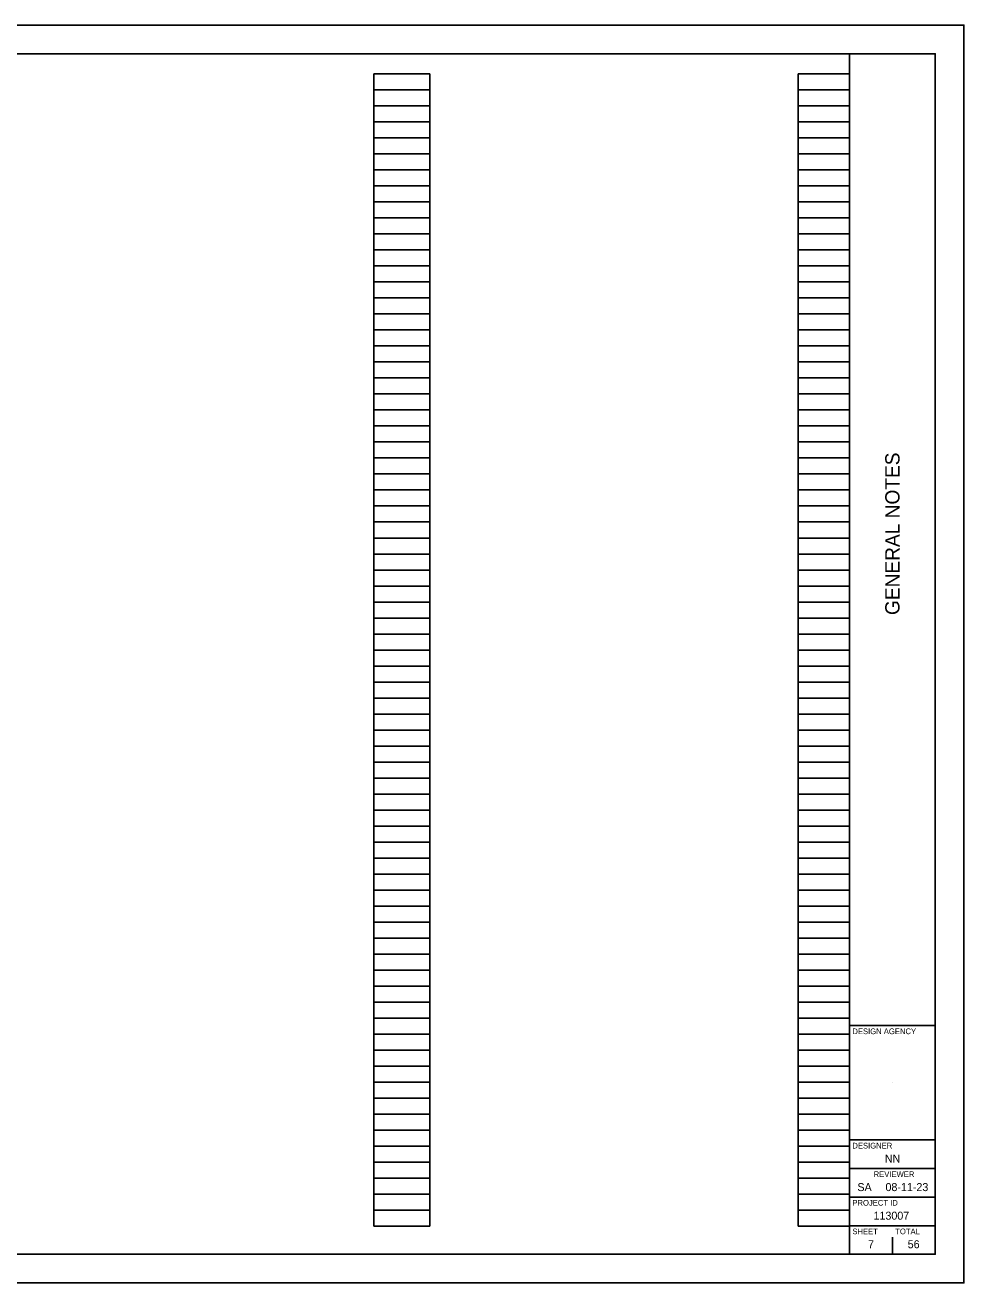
# Model space of a CAD drawing. Extents: x 0 to 34, y -7.4 to 22.
# Drawn here: x 17.58 to 34, y 0 to 22 of the extents above; entities that cross this region are included whole.
import ezdxf

# ---------------------------------------------------------------- set-up
doc = ezdxf.new("R2010")
doc.units = 0
for name, color, linetype in [('SH_Border', 7, 'Continuous'), ('SH_Cut_Line', 7, 'Continuous'), ('SH_Data', 7, 'Continuous')]:
    doc.layers.add(name, color=color, linetype=linetype)

msp = doc.modelspace()

# ---------------------------------------------------------------- linework, layer by layer
at = {"layer": 'SH_Border'}
for p, q in [((32, 0.5), (32, 21.5)), ((32, 4.5), (33.5, 4.5)), ((32, 2.5), (33.5, 2.5)), ((32, 2), (33.5, 2)), ((32, 1.5), (33.5, 1.5)), ((32, 1), (33.5, 1))]:
    msp.add_line(p, q, dxfattribs=at)
msp.add_lwpolyline([(1.5, 21.5), (33.5, 21.5), (33.5, 0.5), (1.5, 0.5)], close=True, dxfattribs=at)
at = {"layer": 'SH_Cut_Line'}
msp.add_lwpolyline([(0, 0), (34, 0), (34, 22), (0, 22)], close=True, dxfattribs=at)
at = {"layer": 'SH_Data'}
for p, q in [((23.68, 0.989), (23.68, 21.149)), ((23.68, 21.149), (24.66, 21.149)), ((24.66, 0.989), (24.66, 21.149)), ((31.1, 0.989), (31.1, 21.149)), ((31.1, 21.149), (32, 21.149)), ((32, 0.989), (32, 21.149)), ((23.68, 20.869), (24.66, 20.869)), ((31.1, 20.869), (32, 20.869)), ((23.68, 20.589), (24.66, 20.589)), ((31.1, 20.589), (32, 20.589)), ((23.68, 20.309), (24.66, 20.309)), ((31.1, 20.309), (32, 20.309)), ((23.68, 20.029), (24.66, 20.029)), ((31.1, 20.029), (32, 20.029)), ((23.68, 19.749), (24.66, 19.749)), ((31.1, 19.749), (32, 19.749)), ((23.68, 19.469), (24.66, 19.469)), ((31.1, 19.469), (32, 19.469)), ((23.68, 19.189), (24.66, 19.189)), ((31.1, 19.189), (32, 19.189)), ((23.68, 18.909), (24.66, 18.909)), ((31.1, 18.909), (32, 18.909)), ((23.68, 18.629), (24.66, 18.629)), ((31.1, 18.629), (32, 18.629)), ((23.68, 18.349), (24.66, 18.349)), ((31.1, 18.349), (32, 18.349)), ((23.68, 18.069), (24.66, 18.069)), ((31.1, 18.069), (32, 18.069)), ((23.68, 17.789), (24.66, 17.789)), ((31.1, 17.789), (32, 17.789)), ((23.68, 17.509), (24.66, 17.509)), ((31.1, 17.509), (32, 17.509)), ((23.68, 17.229), (24.66, 17.229)), ((31.1, 17.229), (32, 17.229)), ((23.68, 16.949), (24.66, 16.949)), ((31.1, 16.949), (32, 16.949)), ((23.68, 16.669), (24.66, 16.669)), ((31.1, 16.669), (32, 16.669)), ((23.68, 16.389), (24.66, 16.389)), ((31.1, 16.389), (32, 16.389)), ((23.68, 16.109), (24.66, 16.109)), ((31.1, 16.109), (32, 16.109)), ((23.68, 15.829), (24.66, 15.829)), ((31.1, 15.829), (32, 15.829)), ((23.68, 15.549), (24.66, 15.549)), ((31.1, 15.549), (32, 15.549)), ((23.68, 15.269), (24.66, 15.269)), ((31.1, 15.269), (32, 15.269)), ((23.68, 14.989), (24.66, 14.989)), ((31.1, 14.989), (32, 14.989)), ((23.68, 14.709), (24.66, 14.709)), ((31.1, 14.709), (32, 14.709)), ((23.68, 14.429), (24.66, 14.429)), ((31.1, 14.429), (32, 14.429)), ((23.68, 14.149), (24.66, 14.149)), ((31.1, 14.149), (32, 14.149)), ((23.68, 13.869), (24.66, 13.869)), ((31.1, 13.869), (32, 13.869)), ((23.68, 13.589), (24.66, 13.589)), ((31.1, 13.589), (32, 13.589)), ((23.68, 13.309), (24.66, 13.309)), ((31.1, 13.309), (32, 13.309)), ((23.68, 13.029), (24.66, 13.029)), ((31.1, 13.029), (32, 13.029)), ((23.68, 12.749), (24.66, 12.749)), ((31.1, 12.749), (32, 12.749)), ((23.68, 12.469), (24.66, 12.469)), ((31.1, 12.469), (32, 12.469)), ((23.68, 12.189), (24.66, 12.189)), ((31.1, 12.189), (32, 12.189)), ((23.68, 11.909), (24.66, 11.909)), ((31.1, 11.909), (32, 11.909)), ((23.68, 11.629), (24.66, 11.629)), ((31.1, 11.629), (32, 11.629)), ((23.68, 11.349), (24.66, 11.349)), ((31.1, 11.349), (32, 11.349)), ((23.68, 11.069), (24.66, 11.069)), ((31.1, 11.069), (32, 11.069)), ((23.68, 10.789), (24.66, 10.789)), ((31.1, 10.789), (32, 10.789)), ((23.68, 10.509), (24.66, 10.509)), ((31.1, 10.509), (32, 10.509)), ((23.68, 10.229), (24.66, 10.229)), ((31.1, 10.229), (32, 10.229)), ((23.68, 9.949), (24.66, 9.949)), ((31.1, 9.949), (32, 9.949)), ((23.68, 9.669), (24.66, 9.669)), ((31.1, 9.669), (32, 9.669)), ((23.68, 9.389), (24.66, 9.389)), ((31.1, 9.389), (32, 9.389)), ((23.68, 9.109), (24.66, 9.109)), ((31.1, 9.109), (32, 9.109)), ((23.68, 8.829), (24.66, 8.829)), ((31.1, 8.829), (32, 8.829)), ((23.68, 8.549), (24.66, 8.549)), ((31.1, 8.549), (32, 8.549)), ((23.68, 8.269), (24.66, 8.269)), ((31.1, 8.269), (32, 8.269)), ((23.68, 7.989), (24.66, 7.989)), ((31.1, 7.989), (32, 7.989)), ((23.68, 7.709), (24.66, 7.709)), ((31.1, 7.709), (32, 7.709)), ((23.68, 7.429), (24.66, 7.429)), ((31.1, 7.429), (32, 7.429)), ((23.68, 7.149), (24.66, 7.149)), ((31.1, 7.149), (32, 7.149)), ((23.68, 6.869), (24.66, 6.869)), ((31.1, 6.869), (32, 6.869)), ((23.68, 6.589), (24.66, 6.589)), ((31.1, 6.589), (32, 6.589)), ((23.68, 6.309), (24.66, 6.309)), ((31.1, 6.309), (32, 6.309)), ((23.68, 6.029), (24.66, 6.029)), ((31.1, 6.029), (32, 6.029)), ((23.68, 5.749), (24.66, 5.749)), ((31.1, 5.749), (32, 5.749)), ((23.68, 5.469), (24.66, 5.469)), ((31.1, 5.469), (32, 5.469)), ((23.68, 5.189), (24.66, 5.189)), ((31.1, 5.189), (32, 5.189)), ((23.68, 4.909), (24.66, 4.909)), ((31.1, 4.909), (32, 4.909)), ((23.68, 4.629), (24.66, 4.629)), ((31.1, 4.629), (32, 4.629)), ((23.68, 4.349), (24.66, 4.349)), ((31.1, 4.349), (32, 4.349)), ((23.68, 4.069), (24.66, 4.069)), ((31.1, 4.069), (32, 4.069)), ((23.68, 3.789), (24.66, 3.789)), ((31.1, 3.789), (32, 3.789)), ((23.68, 3.509), (24.66, 3.509)), ((31.1, 3.509), (32, 3.509)), ((32.75, 3.5), (32.75, 3.5)), ((23.68, 3.229), (24.66, 3.229)), ((31.1, 3.229), (32, 3.229)), ((23.68, 2.949), (24.66, 2.949)), ((31.1, 2.949), (32, 2.949)), ((23.68, 2.669), (24.66, 2.669)), ((31.1, 2.669), (32, 2.669)), ((23.68, 2.389), (24.66, 2.389)), ((31.1, 2.389), (32, 2.389)), ((23.68, 2.109), (24.66, 2.109)), ((31.1, 2.109), (32, 2.109)), ((23.68, 1.829), (24.66, 1.829)), ((31.1, 1.829), (32, 1.829)), ((23.68, 1.549), (24.66, 1.549)), ((31.1, 1.549), (32, 1.549)), ((23.68, 1.269), (24.66, 1.269)), ((31.1, 1.269), (32, 1.269)), ((23.68, 0.989), (24.66, 0.989)), ((31.1, 0.989), (32, 0.989)), ((32.375, 0.675), (32.375, 0.675)), ((32.75, 0.5), (32.75, 0.8))]:
    msp.add_line(p, q, dxfattribs=at)

# ---------------------------------------------------------------- texts
msp.add_text('GENERAL NOTES', height=0.25, rotation=90, dxfattribs=at).set_placement((32.875, 11.682))
for s, height, p in [('DESIGN AGENCY', 0.1, (32.05, 4.35)), ('DESIGNER', 0.1, (32.05, 2.35)), ('NN', 0.14, (32.617, 2.105)), ('REVIEWER', 0.1, (32.422, 1.85)), ('SA', 0.14, (32.138, 1.605)), ('08-11-23', 0.14, (32.629, 1.605)), ('PROJECT ID', 0.1, (32.05, 1.35)), ('113007', 0.14, (32.42, 1.105)), ('SHEET', 0.1, (32.05, 0.85)), ('TOTAL', 0.1, (32.8, 0.85)), ('7', 0.14, (32.324, 0.605)), ('56', 0.14, (33.018, 0.605))]:
    msp.add_text(s, height=height, dxfattribs=at).set_placement(p)

doc.saveas('drawing.dxf')
